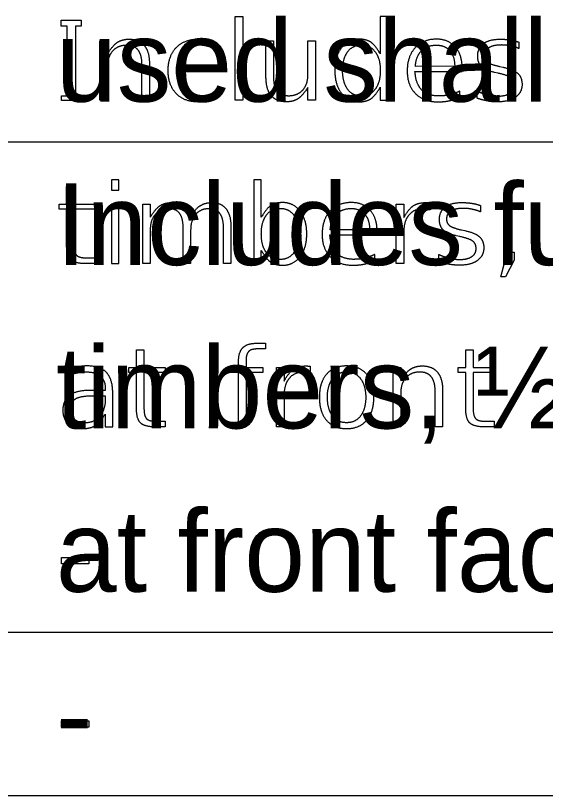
# Model space of a CAD drawing. Extents: x 0.11 to 2.72, y -0.17 to 1.89.
# Drawn here: x 1.1207 to 1.2017, y 1.158 to 1.2773 of the extents above; entities that cross this region are included whole.
import ezdxf

# ---------------------------------------------------------------- set-up
doc = ezdxf.new("R2010")
doc.units = 0
doc.layers.add('SheetGridMinor', color=7, linetype='Continuous')
doc.layers.add('SheetText', color=7, linetype='Continuous')

msp = doc.modelspace()

# ---------------------------------------------------------------- linework, layer by layer
at = {"layer": 'SheetGridMinor'}
for p, q in [((0.15055, 1.25802), (1.94932, 1.25802)), ((0.15035, 1.18302), (1.94912, 1.18302)), ((0.15035, 1.15802), (1.94912, 1.15802))]:
    msp.add_line(p, q, dxfattribs=at)
at = {"layer": 'SheetText'}
for p, q in [((1.15114, 1.27322), (1.15114, 1.27225)), ((1.19764, 1.27329), (1.19764, 1.27231)), ((1.1707, 1.26894), (1.1707, 1.26894)), ((1.18785, 1.26959), (1.18183, 1.26958)), ((1.19448, 1.26853), (1.19394, 1.26866)), ((1.19471, 1.26956), (1.19525, 1.26944)), ((1.15114, 1.26564), (1.15114, 1.26469)), ((1.18863, 1.26481), (1.18863, 1.26579)), ((1.19129, 1.26469), (1.19129, 1.2658)), ((1.18407, 1.24868), (1.18407, 1.24763)), ((1.19179, 1.24829), (1.19179, 1.24731)), ((1.14736, 1.24637), (1.14736, 1.24637)), ((1.17484, 1.24459), (1.16881, 1.24458)), ((1.16402, 1.24394), (1.16402, 1.24394)), ((1.18864, 1.24353), (1.18809, 1.24366)), ((1.18887, 1.24456), (1.1894, 1.24444)), ((1.17561, 1.23981), (1.17561, 1.24079)), ((1.18544, 1.23969), (1.18544, 1.2408)), ((1.12861, 1.22314), (1.12861, 1.22219)), ((1.16576, 1.22368), (1.16576, 1.22263)), ((1.17131, 1.22374), (1.17131, 1.22374)), ((1.17131, 1.22283), (1.17131, 1.22283))]:
    msp.add_line(p, q, dxfattribs=at)
for points in [[(1.15429, 1.27722), (1.15543, 1.27722), (1.15543, 1.2644), (1.15429, 1.2644)], [(1.12858, 1.27575), (1.12767, 1.27575), (1.12767, 1.27666), (1.13072, 1.27666), (1.13072, 1.27575), (1.12987, 1.27575), (1.12987, 1.26507), (1.13072, 1.26507), (1.13072, 1.26435), (1.12771, 1.26435), (1.12771, 1.26507), (1.12858, 1.26507)], [(1.13535, 1.25222), (1.13535, 1.25066), (1.13649, 1.25066), (1.13649, 1.25222)], [(1.13535, 1.24851), (1.13535, 1.2394), (1.13649, 1.2394), (1.13649, 1.24851)], [(1.19556, 1.24113), (1.19693, 1.24113), (1.19693, 1.23993), (1.19562, 1.23737), (1.19492, 1.23737), (1.19556, 1.23986)], [(1.12772, 1.19444), (1.13188, 1.19444), (1.13188, 1.19347), (1.12772, 1.19347)], [(1.12772, 1.16944), (1.13188, 1.16944), (1.13188, 1.16847), (1.12772, 1.16847)]]:
    msp.add_lwpolyline(points, close=True, dxfattribs=at)
for points in [[(1.17647, 1.26641), (1.17647, 1.2644), (1.17761, 1.2644), (1.17761, 1.27722), (1.17647, 1.27722), (1.17647, 1.27148)], [(1.13474, 1.26957), (1.13474, 1.2644), (1.13359, 1.2644), (1.13359, 1.27351), (1.13474, 1.27351), (1.13474, 1.27152)], [(1.15898, 1.26795), (1.15898, 1.27351), (1.16012, 1.27351), (1.16012, 1.26801)], [(1.1654, 1.26831), (1.1654, 1.27351), (1.16654, 1.27351), (1.16654, 1.2644), (1.1654, 1.2644), (1.1654, 1.26636)], [(1.14115, 1.26994), (1.14115, 1.2644), (1.14001, 1.2644), (1.14001, 1.26989)], [(1.18177, 1.26879), (1.18899, 1.26879), (1.18899, 1.26934)], [(1.15827, 1.24648), (1.15827, 1.25222), (1.15712, 1.25222), (1.15712, 1.2394), (1.15827, 1.2394), (1.15827, 1.24141)], [(1.12848, 1.24232), (1.12848, 1.24771), (1.12733, 1.24771), (1.12733, 1.24851), (1.12848, 1.24851), (1.12848, 1.25121), (1.12963, 1.25121), (1.12963, 1.24851), (1.13286, 1.24851), (1.13286, 1.24771), (1.12963, 1.24771), (1.12963, 1.24232)], [(1.14128, 1.24457), (1.14128, 1.2394), (1.14014, 1.2394), (1.14014, 1.24851), (1.14128, 1.24851), (1.14128, 1.24648)], [(1.18006, 1.24421), (1.18006, 1.2394), (1.17891, 1.2394), (1.17891, 1.24851), (1.18006, 1.24851), (1.18006, 1.24643)], [(1.14746, 1.24457), (1.14746, 1.2394), (1.14631, 1.2394), (1.14631, 1.24489)], [(1.15363, 1.24494), (1.15363, 1.2394), (1.15248, 1.2394), (1.15248, 1.24489)], [(1.16876, 1.24379), (1.17598, 1.24379), (1.17598, 1.24434)], [(1.13146, 1.24028), (1.13286, 1.24028), (1.13286, 1.2394), (1.13146, 1.2394)], [(1.15766, 1.22722), (1.15893, 1.22722), (1.15893, 1.22634), (1.15764, 1.22634)], [(1.13917, 1.21732), (1.13917, 1.22271), (1.13802, 1.22271), (1.13802, 1.22351), (1.13917, 1.22351), (1.13917, 1.22621), (1.14032, 1.22621), (1.14032, 1.22351), (1.14354, 1.22351), (1.14354, 1.22271), (1.14032, 1.22271), (1.14032, 1.21732)], [(1.18953, 1.21732), (1.18953, 1.22271), (1.18838, 1.22271), (1.18838, 1.22351), (1.18953, 1.22351), (1.18953, 1.22621), (1.19067, 1.22621), (1.19067, 1.22351), (1.1939, 1.22351), (1.1939, 1.22271), (1.19067, 1.22271), (1.19067, 1.21732)], [(1.15593, 1.22456), (1.15593, 1.22351), (1.15851, 1.22351), (1.15851, 1.22271), (1.15593, 1.22271), (1.15593, 1.2144), (1.15478, 1.2144), (1.15478, 1.22271), (1.15329, 1.22271), (1.15329, 1.22351), (1.15478, 1.22351), (1.15478, 1.22438)], [(1.16175, 1.21921), (1.16175, 1.2144), (1.16061, 1.2144), (1.16061, 1.22351), (1.16175, 1.22351), (1.16175, 1.22143)], [(1.17959, 1.21957), (1.17959, 1.2144), (1.17844, 1.2144), (1.17844, 1.22351), (1.17959, 1.22351), (1.17959, 1.22152)], [(1.1344, 1.22036), (1.1344, 1.21999), (1.13199, 1.21999)], [(1.1344, 1.21638), (1.1344, 1.2144), (1.13554, 1.2144), (1.13554, 1.21962)], [(1.186, 1.21994), (1.186, 1.2144), (1.18486, 1.2144), (1.18486, 1.21989)], [(1.13263, 1.21919), (1.1344, 1.21919), (1.1344, 1.21863)], [(1.14215, 1.21528), (1.14354, 1.21528), (1.14354, 1.2144), (1.14215, 1.2144)], [(1.19251, 1.21528), (1.1939, 1.21528), (1.1939, 1.2144), (1.19251, 1.2144)]]:
    msp.add_lwpolyline(points, dxfattribs=at)
for points in [[(1.13474, 1.27152), (1.13567, 1.27294), (1.13639, 1.27334)], [(1.13639, 1.27334), (1.1371, 1.27374), (1.13804, 1.27374)], [(1.13804, 1.27374), (1.13958, 1.27374), (1.14037, 1.27279)], [(1.14525, 1.27246), (1.14647, 1.27374), (1.1486, 1.27374)], [(1.1486, 1.27374), (1.1493, 1.27374), (1.14997, 1.27359)], [(1.14997, 1.27359), (1.15064, 1.27345), (1.15114, 1.27322)], [(1.1732, 1.27374), (1.17157, 1.27374), (1.17054, 1.27242)], [(1.1749, 1.27335), (1.1742, 1.27374), (1.1732, 1.27374)], [(1.17647, 1.27148), (1.17561, 1.27296), (1.1749, 1.27335)], [(1.18504, 1.27374), (1.18299, 1.27374), (1.18179, 1.27242)], [(1.18793, 1.27256), (1.18687, 1.27374), (1.18504, 1.27374)], [(1.19224, 1.27306), (1.19312, 1.27374), (1.19481, 1.27374)], [(1.19481, 1.27374), (1.19566, 1.27374), (1.1964, 1.27361)], [(1.1964, 1.27361), (1.19715, 1.27349), (1.19764, 1.27329)], [(1.13769, 1.2728), (1.13633, 1.2728), (1.13553, 1.27193)], [(1.13943, 1.27206), (1.13885, 1.2728), (1.13769, 1.2728)], [(1.14001, 1.26989), (1.14001, 1.27132), (1.13943, 1.27206)], [(1.14037, 1.27279), (1.14115, 1.27184), (1.14115, 1.26994)], [(1.14402, 1.26894), (1.14402, 1.27119), (1.14525, 1.27246)], [(1.14867, 1.27283), (1.14706, 1.27283), (1.14615, 1.2718)], [(1.15007, 1.27264), (1.14938, 1.27283), (1.14867, 1.27283)], [(1.15114, 1.27225), (1.15077, 1.27245), (1.15007, 1.27264)], [(1.17054, 1.27242), (1.16951, 1.27111), (1.16951, 1.26894)], [(1.17146, 1.27179), (1.17223, 1.27285), (1.17358, 1.27285)], [(1.17358, 1.27285), (1.17493, 1.27285), (1.1757, 1.27179)], [(1.18179, 1.27242), (1.18058, 1.27111), (1.18058, 1.26886)], [(1.18183, 1.26958), (1.18197, 1.27124), (1.18282, 1.27204)], [(1.18282, 1.27204), (1.18366, 1.27283), (1.18506, 1.27283)], [(1.18506, 1.27283), (1.18631, 1.27283), (1.18707, 1.272)], [(1.18899, 1.26934), (1.18899, 1.27139), (1.18793, 1.27256)], [(1.19136, 1.27114), (1.19136, 1.27238), (1.19224, 1.27306)], [(1.19311, 1.27245), (1.19245, 1.27204), (1.19245, 1.27121)], [(1.19499, 1.27285), (1.19377, 1.27285), (1.19311, 1.27245)], [(1.19653, 1.27268), (1.19579, 1.27285), (1.19499, 1.27285)], [(1.19764, 1.27231), (1.19727, 1.2725), (1.19653, 1.27268)], [(1.13553, 1.27193), (1.13474, 1.27105), (1.13474, 1.26957)], [(1.14615, 1.2718), (1.14525, 1.27076), (1.14525, 1.26894)], [(1.1707, 1.26894), (1.1707, 1.27074), (1.17146, 1.27179)], [(1.1757, 1.27179), (1.17647, 1.27074), (1.17647, 1.26894)], [(1.18707, 1.272), (1.18784, 1.27117), (1.18785, 1.26959)], [(1.19195, 1.26954), (1.19136, 1.27013), (1.19136, 1.27114)], [(1.19245, 1.27121), (1.19245, 1.27055), (1.19293, 1.2702)], [(1.19293, 1.2702), (1.1934, 1.26985), (1.19471, 1.26956)], [(1.14523, 1.26544), (1.14402, 1.26673), (1.14402, 1.26894)], [(1.14525, 1.26894), (1.14525, 1.26712), (1.14615, 1.26609)], [(1.16951, 1.26894), (1.16951, 1.26677), (1.17054, 1.26546)], [(1.17146, 1.26609), (1.1707, 1.26715), (1.1707, 1.26894)], [(1.17647, 1.26894), (1.17647, 1.26715), (1.1757, 1.26609)], [(1.18058, 1.26886), (1.18058, 1.26668), (1.18185, 1.26541)], [(1.18283, 1.26596), (1.1819, 1.26687), (1.18177, 1.26879)], [(1.19394, 1.26866), (1.19254, 1.26896), (1.19195, 1.26954)], [(1.19648, 1.26782), (1.19599, 1.26821), (1.19448, 1.26853)], [(1.19525, 1.26944), (1.19686, 1.26909), (1.19751, 1.26849)], [(1.19751, 1.26849), (1.19815, 1.26789), (1.19815, 1.26681)], [(1.15977, 1.2651), (1.15898, 1.26606), (1.15898, 1.26795)], [(1.16012, 1.26801), (1.16012, 1.26658), (1.1607, 1.26583)], [(1.1646, 1.26596), (1.1654, 1.26683), (1.1654, 1.26831)], [(1.19697, 1.2667), (1.19697, 1.26744), (1.19648, 1.26782)], [(1.14615, 1.26609), (1.14706, 1.26505), (1.14867, 1.26505)], [(1.1654, 1.26636), (1.16446, 1.26494), (1.16375, 1.26455)], [(1.17358, 1.26503), (1.17223, 1.26503), (1.17146, 1.26609)], [(1.1757, 1.26609), (1.17493, 1.26503), (1.17358, 1.26503)], [(1.1749, 1.26454), (1.17561, 1.26492), (1.17647, 1.26641)], [(1.1963, 1.26546), (1.19697, 1.26589), (1.19697, 1.2667)], [(1.19815, 1.26681), (1.19815, 1.2656), (1.19717, 1.26487)], [(1.1485, 1.26415), (1.14644, 1.26415), (1.14523, 1.26544)], [(1.14867, 1.26505), (1.14938, 1.26505), (1.15007, 1.26524)], [(1.15007, 1.26524), (1.15077, 1.26543), (1.15114, 1.26564)], [(1.16211, 1.26415), (1.16057, 1.26415), (1.15977, 1.2651)], [(1.1607, 1.26583), (1.16128, 1.26509), (1.16244, 1.26509)], [(1.16244, 1.26509), (1.1638, 1.26509), (1.1646, 1.26596)], [(1.17054, 1.26546), (1.17157, 1.26415), (1.1732, 1.26415)], [(1.18185, 1.26541), (1.18312, 1.26415), (1.18532, 1.26415)], [(1.18541, 1.26505), (1.18377, 1.26505), (1.18283, 1.26596)], [(1.18721, 1.26528), (1.18634, 1.26505), (1.18541, 1.26505)], [(1.18863, 1.26579), (1.18808, 1.26551), (1.18721, 1.26528)], [(1.19129, 1.2658), (1.19187, 1.2655), (1.19274, 1.26527)], [(1.19274, 1.26527), (1.19361, 1.26503), (1.19446, 1.26503)], [(1.19717, 1.26487), (1.1962, 1.26415), (1.19442, 1.26415)], [(1.19446, 1.26503), (1.19562, 1.26503), (1.1963, 1.26546)], [(1.14995, 1.2643), (1.14927, 1.26415), (1.1485, 1.26415)], [(1.15114, 1.26469), (1.15063, 1.26445), (1.14995, 1.2643)], [(1.16375, 1.26455), (1.16305, 1.26415), (1.16211, 1.26415)], [(1.1732, 1.26415), (1.1742, 1.26415), (1.1749, 1.26454)], [(1.18532, 1.26415), (1.1862, 1.26415), (1.18707, 1.26433)], [(1.18707, 1.26433), (1.18793, 1.26452), (1.18863, 1.26481)], [(1.19286, 1.26429), (1.19205, 1.26444), (1.19129, 1.26469)], [(1.19442, 1.26415), (1.19368, 1.26415), (1.19286, 1.26429)], [(1.14128, 1.24648), (1.14219, 1.24795), (1.14289, 1.24834)], [(1.14289, 1.24834), (1.14358, 1.24874), (1.14456, 1.24874)], [(1.14456, 1.24874), (1.14553, 1.24874), (1.14621, 1.24825)], [(1.14621, 1.24825), (1.14688, 1.24776), (1.14736, 1.24637)], [(1.14736, 1.24637), (1.14816, 1.24779), (1.14892, 1.24826)], [(1.14892, 1.24826), (1.14969, 1.24874), (1.15074, 1.24874)], [(1.15074, 1.24874), (1.15212, 1.24874), (1.15288, 1.24776)], [(1.15983, 1.24835), (1.15913, 1.24796), (1.15827, 1.24648)], [(1.16153, 1.24874), (1.16053, 1.24874), (1.15983, 1.24835)], [(1.16419, 1.24742), (1.16316, 1.24874), (1.16153, 1.24874)], [(1.17203, 1.24874), (1.16998, 1.24874), (1.16877, 1.24742)], [(1.17492, 1.24756), (1.17386, 1.24874), (1.17203, 1.24874)], [(1.18006, 1.24643), (1.18092, 1.24794), (1.18166, 1.24834)], [(1.18166, 1.24834), (1.1824, 1.24874), (1.18349, 1.24874)], [(1.18349, 1.24874), (1.18364, 1.24874), (1.18382, 1.24871)], [(1.18382, 1.24871), (1.18401, 1.24869), (1.18407, 1.24868)], [(1.18639, 1.24806), (1.18727, 1.24874), (1.18896, 1.24874)], [(1.18896, 1.24874), (1.18981, 1.24874), (1.19056, 1.24861)], [(1.19056, 1.24861), (1.1913, 1.24849), (1.19179, 1.24829)], [(1.14411, 1.2478), (1.14282, 1.2478), (1.14205, 1.24692)], [(1.14577, 1.24707), (1.14524, 1.2478), (1.14411, 1.2478)], [(1.14631, 1.24489), (1.14631, 1.24634), (1.14577, 1.24707)], [(1.1503, 1.2478), (1.14899, 1.2478), (1.14822, 1.24692)], [(1.15194, 1.24706), (1.15141, 1.2478), (1.1503, 1.2478)], [(1.15248, 1.24489), (1.15248, 1.24633), (1.15194, 1.24706)], [(1.15288, 1.24776), (1.15363, 1.24679), (1.15363, 1.24494)], [(1.15903, 1.24679), (1.15979, 1.24785), (1.16114, 1.24785)], [(1.16114, 1.24785), (1.1625, 1.24785), (1.16326, 1.24679)], [(1.16522, 1.24394), (1.16522, 1.24611), (1.16419, 1.24742)], [(1.16877, 1.24742), (1.16757, 1.24611), (1.16757, 1.24386)], [(1.16881, 1.24458), (1.16895, 1.24624), (1.1698, 1.24704)], [(1.1698, 1.24704), (1.17065, 1.24783), (1.17205, 1.24783)], [(1.17205, 1.24783), (1.1733, 1.24783), (1.17406, 1.247)], [(1.17406, 1.247), (1.17482, 1.24617), (1.17484, 1.24459)], [(1.17598, 1.24434), (1.17598, 1.24639), (1.17492, 1.24756)], [(1.18303, 1.24777), (1.1816, 1.24777), (1.18083, 1.24683)], [(1.18377, 1.24769), (1.18343, 1.24777), (1.18303, 1.24777)], [(1.18407, 1.24762), (1.18402, 1.24762), (1.18377, 1.24769)], [(1.18407, 1.24763), (1.18407, 1.24762), (1.18407, 1.24762)], [(1.18551, 1.24614), (1.18551, 1.24738), (1.18639, 1.24806)], [(1.18726, 1.24745), (1.1866, 1.24704), (1.1866, 1.24621)], [(1.18915, 1.24785), (1.18792, 1.24785), (1.18726, 1.24745)], [(1.19068, 1.24768), (1.18994, 1.24785), (1.18915, 1.24785)], [(1.19179, 1.24731), (1.19142, 1.2475), (1.19068, 1.24768)], [(1.14205, 1.24692), (1.14128, 1.24604), (1.14128, 1.24457)], [(1.14822, 1.24692), (1.14746, 1.24605), (1.14746, 1.24457)], [(1.15827, 1.24394), (1.15827, 1.24574), (1.15903, 1.24679)], [(1.16326, 1.24679), (1.16402, 1.24574), (1.16402, 1.24394)], [(1.18083, 1.24683), (1.18006, 1.2459), (1.18006, 1.24421)], [(1.1861, 1.24454), (1.18551, 1.24513), (1.18551, 1.24614)], [(1.1866, 1.24621), (1.1866, 1.24555), (1.18708, 1.2452)], [(1.18708, 1.2452), (1.18755, 1.24485), (1.18887, 1.24456)], [(1.15903, 1.24109), (1.15827, 1.24215), (1.15827, 1.24394)], [(1.16402, 1.24394), (1.16402, 1.24215), (1.16326, 1.24109)], [(1.16419, 1.24046), (1.16522, 1.24177), (1.16522, 1.24394)], [(1.16757, 1.24386), (1.16757, 1.24168), (1.16884, 1.24041)], [(1.16982, 1.24096), (1.16889, 1.24187), (1.16876, 1.24379)], [(1.18809, 1.24366), (1.18669, 1.24396), (1.1861, 1.24454)], [(1.19063, 1.24282), (1.19014, 1.24321), (1.18864, 1.24353)], [(1.1894, 1.24444), (1.19101, 1.24409), (1.19166, 1.24349)], [(1.19166, 1.24349), (1.1923, 1.24289), (1.1923, 1.24181)], [(1.12911, 1.24001), (1.12848, 1.24062), (1.12848, 1.24232)], [(1.12963, 1.24232), (1.12963, 1.24107), (1.13001, 1.24068)], [(1.19112, 1.24169), (1.19112, 1.24244), (1.19063, 1.24282)], [(1.15827, 1.24141), (1.15913, 1.23992), (1.15983, 1.23954)], [(1.16114, 1.24003), (1.15979, 1.24003), (1.15903, 1.24109)], [(1.16326, 1.24109), (1.1625, 1.24003), (1.16114, 1.24003)], [(1.19045, 1.24046), (1.19112, 1.24089), (1.19112, 1.24169)], [(1.1923, 1.24181), (1.1923, 1.2406), (1.19133, 1.23987)], [(1.13146, 1.2394), (1.12973, 1.2394), (1.12911, 1.24001)], [(1.13001, 1.24068), (1.13039, 1.24028), (1.13146, 1.24028)], [(1.16153, 1.23915), (1.16316, 1.23915), (1.16419, 1.24046)], [(1.16884, 1.24041), (1.1701, 1.23915), (1.1723, 1.23915)], [(1.17239, 1.24005), (1.17075, 1.24005), (1.16982, 1.24096)], [(1.1742, 1.24028), (1.17332, 1.24005), (1.17239, 1.24005)], [(1.17405, 1.23933), (1.17491, 1.23952), (1.17561, 1.23981)], [(1.17561, 1.24079), (1.17507, 1.24051), (1.1742, 1.24028)], [(1.18544, 1.2408), (1.18602, 1.2405), (1.18689, 1.24027)], [(1.18689, 1.24027), (1.18776, 1.24003), (1.18861, 1.24003)], [(1.19133, 1.23987), (1.19035, 1.23915), (1.18858, 1.23915)], [(1.18861, 1.24003), (1.18978, 1.24003), (1.19045, 1.24046)], [(1.15983, 1.23954), (1.16053, 1.23915), (1.16153, 1.23915)], [(1.1723, 1.23915), (1.17319, 1.23915), (1.17405, 1.23933)], [(1.18701, 1.23929), (1.1862, 1.23944), (1.18544, 1.23969)], [(1.18858, 1.23915), (1.18783, 1.23915), (1.18701, 1.23929)], [(1.15546, 1.22655), (1.15614, 1.22722), (1.15766, 1.22722)], [(1.15478, 1.22438), (1.15478, 1.22589), (1.15546, 1.22655)], [(1.15632, 1.22594), (1.15593, 1.22553), (1.15593, 1.22456)], [(1.15764, 1.22634), (1.15671, 1.22634), (1.15632, 1.22594)], [(1.13011, 1.22357), (1.12932, 1.22341), (1.12861, 1.22314)], [(1.13164, 1.22374), (1.1309, 1.22374), (1.13011, 1.22357)], [(1.13458, 1.22273), (1.13362, 1.22374), (1.13164, 1.22374)], [(1.16175, 1.22143), (1.16261, 1.22294), (1.16336, 1.22334)], [(1.16336, 1.22334), (1.1641, 1.22374), (1.16518, 1.22374)], [(1.16518, 1.22374), (1.16533, 1.22374), (1.16551, 1.22371)], [(1.16551, 1.22371), (1.1657, 1.22369), (1.16576, 1.22368)], [(1.17131, 1.22374), (1.16936, 1.22374), (1.16825, 1.22248)], [(1.17437, 1.22248), (1.17326, 1.22374), (1.17131, 1.22374)], [(1.17959, 1.22152), (1.18052, 1.22294), (1.18123, 1.22334)], [(1.18123, 1.22334), (1.18195, 1.22374), (1.18288, 1.22374)], [(1.18288, 1.22374), (1.18442, 1.22374), (1.18521, 1.22279)], [(1.12861, 1.22219), (1.12904, 1.22242), (1.12984, 1.22263)], [(1.12984, 1.22263), (1.13064, 1.22283), (1.13148, 1.22283)], [(1.13148, 1.22283), (1.13284, 1.22283), (1.13362, 1.22219)], [(1.13362, 1.22219), (1.1344, 1.22154), (1.1344, 1.22036)], [(1.13554, 1.21962), (1.13554, 1.22172), (1.13458, 1.22273)], [(1.16472, 1.22277), (1.16329, 1.22277), (1.16252, 1.22183)], [(1.16546, 1.22269), (1.16512, 1.22277), (1.16472, 1.22277)], [(1.16576, 1.22262), (1.16571, 1.22262), (1.16546, 1.22269)], [(1.16576, 1.22263), (1.16576, 1.22262), (1.16576, 1.22262)], [(1.16825, 1.22248), (1.16715, 1.22122), (1.16715, 1.21894)], [(1.16916, 1.22178), (1.16994, 1.22283), (1.17131, 1.22283)], [(1.17131, 1.22283), (1.17268, 1.22283), (1.17346, 1.22177)], [(1.17548, 1.21894), (1.17548, 1.22122), (1.17437, 1.22248)], [(1.18038, 1.22193), (1.17959, 1.22105), (1.17959, 1.21957)], [(1.18253, 1.2228), (1.18117, 1.2228), (1.18038, 1.22193)], [(1.18427, 1.22206), (1.18369, 1.2228), (1.18253, 1.2228)], [(1.18486, 1.21989), (1.18486, 1.22132), (1.18427, 1.22206)], [(1.18521, 1.22279), (1.186, 1.22184), (1.186, 1.21994)], [(1.16252, 1.22183), (1.16175, 1.2209), (1.16175, 1.21921)], [(1.16838, 1.21894), (1.16838, 1.22072), (1.16916, 1.22178)], [(1.17346, 1.22177), (1.17424, 1.2207), (1.17424, 1.21894)], [(1.13199, 1.21999), (1.12992, 1.21999), (1.12892, 1.21923)], [(1.12892, 1.21923), (1.12791, 1.21847), (1.12791, 1.21696)], [(1.12905, 1.21706), (1.12905, 1.21823), (1.12986, 1.21871)], [(1.12986, 1.21871), (1.13067, 1.21919), (1.13263, 1.21919)], [(1.1344, 1.21863), (1.1344, 1.21702), (1.13356, 1.21603)], [(1.16715, 1.21894), (1.16715, 1.21668), (1.16825, 1.21541)], [(1.16916, 1.21611), (1.16838, 1.21716), (1.16838, 1.21894)], [(1.17424, 1.21894), (1.17424, 1.21717), (1.17346, 1.21611)], [(1.17437, 1.21541), (1.17548, 1.21668), (1.17548, 1.21894)], [(1.13979, 1.21501), (1.13917, 1.21562), (1.13917, 1.21732)], [(1.14032, 1.21732), (1.14032, 1.21607), (1.1407, 1.21568)], [(1.19015, 1.21501), (1.18953, 1.21562), (1.18953, 1.21732)], [(1.19067, 1.21732), (1.19067, 1.21607), (1.19105, 1.21568)], [(1.12791, 1.21696), (1.12791, 1.21567), (1.12871, 1.21491)], [(1.12967, 1.21558), (1.12905, 1.21613), (1.12905, 1.21706)], [(1.13356, 1.21603), (1.13271, 1.21503), (1.13131, 1.21503)], [(1.13275, 1.21454), (1.1335, 1.21492), (1.1344, 1.21638)], [(1.17131, 1.21505), (1.16993, 1.21505), (1.16916, 1.21611)], [(1.17346, 1.21611), (1.17268, 1.21505), (1.17131, 1.21505)], [(1.12871, 1.21491), (1.12951, 1.21415), (1.13089, 1.21415)], [(1.13131, 1.21503), (1.13028, 1.21503), (1.12967, 1.21558)], [(1.14215, 1.2144), (1.14042, 1.2144), (1.13979, 1.21501)], [(1.1407, 1.21568), (1.14108, 1.21528), (1.14215, 1.21528)], [(1.16825, 1.21541), (1.16936, 1.21415), (1.17131, 1.21415)], [(1.17131, 1.21415), (1.17326, 1.21415), (1.17437, 1.21541)], [(1.19251, 1.2144), (1.19078, 1.2144), (1.19015, 1.21501)], [(1.19105, 1.21568), (1.19143, 1.21528), (1.19251, 1.21528)], [(1.13089, 1.21415), (1.132, 1.21415), (1.13275, 1.21454)]]:
    msp.add_open_spline(points, degree=2, dxfattribs=at)

# ---------------------------------------------------------------- texts
for s, p in [('used shall be foamed cellular concrete.', (1.12686, 1.26418)), ('Includes furnishing and placing engineering fabric, macadam stone, 4" x 6" treated ', (1.12686, 1.23918)), ('timbers, ½" diameter steel pins (or rebars), porous backfill or granular subbase backfill ', (1.12686, 1.21418)), ('at front face of abutment footing, and all required excavating, shaping, and compacting. ', (1.12686, 1.18918)), ('-', (1.12686, 1.16418))]:
    msp.add_text(s, height=0.0125, dxfattribs=at).set_placement(p)

doc.saveas('drawing.dxf')
